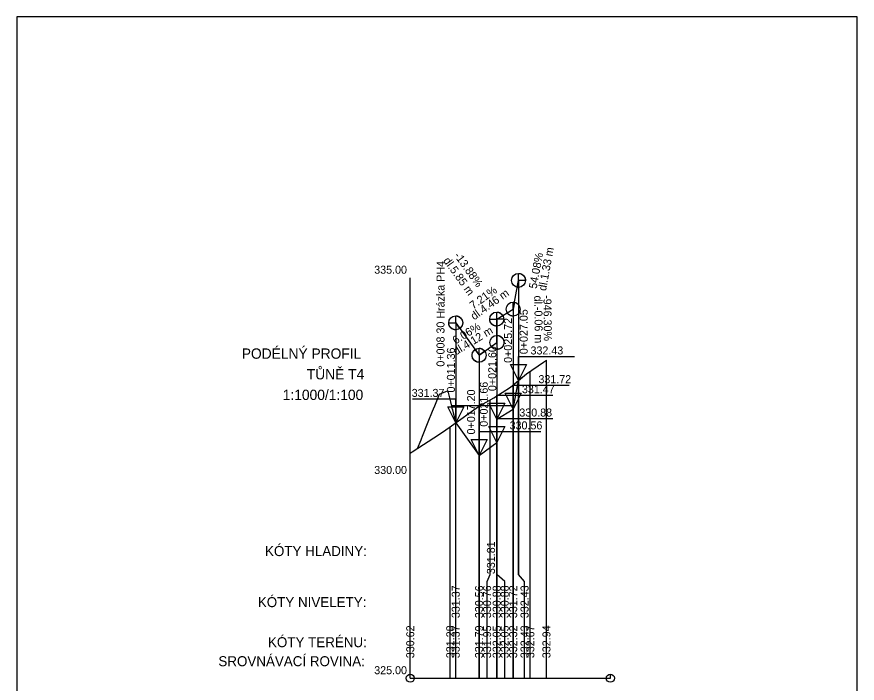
# Model space of a CAD drawing. Extents: x -559294 to -559084, y -1163838 to -1163541.
# Drawn here: x -559293.9 to -559083.9, y -1163707.7 to -1163541.3 of the extents above; entities that cross this region are included whole.
import ezdxf

# ---------------------------------------------------------------- set-up
doc = ezdxf.new("R2010")
doc.units = 0
for name, color, linetype in [('13', 7, 'Continuous'), ('14', 7, 'Continuous'), ('16', 7, 'Continuous'), ('4', 7, 'Continuous'), ('46', 7, 'Continuous'), ('56', 7, 'Continuous'), ('8', 7, 'Continuous'), ('_PP', 7, 'Continuous')]:
    doc.layers.add(name, color=color, linetype=linetype)

msp = doc.modelspace()

# ---------------------------------------------------------------- linework, layer by layer
for p, q in [((-559083.87, -1163541.29), (-559293.87, -1163541.29)), ((-559293.87, -1163541.29), (-559293.87, -1163838.29)), ((-559083.87, -1163838.29), (-559083.87, -1163541.29)), ((-559184.19, -1163617.69), (-559184.19, -1163642.69)), ((-559161.52, -1163706.43), (-559161.52, -1163627.03)), ((-559165.55, -1163706.43), (-559165.55, -1163629.73)), ((-559169.83, -1163639.26), (-559168.5, -1163632.09)), ((-559169.83, -1163706.43), (-559169.83, -1163633.23)), ((-559173.95, -1163706.43), (-559173.95, -1163635.93)), ((-559178.35, -1163706.43), (-559178.35, -1163638.53)), ((-559173.95, -1163641.76), (-559169.83, -1163639.26)), ((-559184.19, -1163642.69), (-559178.35, -1163650.8)), ((-559184.19, -1163706.43), (-559184.19, -1163642.73)), ((-559173.95, -1163641.76), (-559173.89, -1163647.59)), ((-559185.55, -1163706.43), (-559185.55, -1163643.63)), ((-559178.35, -1163650.8), (-559173.89, -1163647.59)), ((-559195.55, -1163706.43), (-559195.55, -1163650.23)), ((-559176.35, -1163706.43), (-559176.35, -1163682.29)), ((-559171.95, -1163706.43), (-559171.95, -1163682.29)), ((-559166.99, -1163706.43), (-559166.99, -1163682.29))]:
    msp.add_line(p, q)
for points in [[(-559195.55, -1163650.25), (-559195.05, -1163649.9), (-559188.27, -1163645.53), (-559187.67, -1163645.07), (-559187.22, -1163644.8), (-559185.26, -1163643.45), (-559178.49, -1163638.58), (-559174.68, -1163636.43), (-559170.51, -1163633.76), (-559166.5, -1163630.43), (-559162.29, -1163627.5), (-559161.52, -1163627.01)], [(-559166.99, -1163682.29), (-559168.5, -1163680.54), (-559168.5, -1163632.13)], [(-559167.71, -1163631.44), (-559167.34, -1163631.13)], [(-559193.72, -1163649.05), (-559192.85, -1163646.89), (-559192.75, -1163646.62), (-559192.48, -1163645.96), (-559191.04, -1163642.38), (-559189.98, -1163639.77), (-559189.73, -1163639.14), (-559189.42, -1163638.39), (-559188.25, -1163635.48), (-559188.05, -1163635.4), (-559187.23, -1163635.08), (-559187.13, -1163635.03), (-559187.04, -1163635), (-559186.81, -1163634.91), (-559186.67, -1163634.85), (-559186.22, -1163634.67), (-559186.12, -1163635.04), (-559186.1, -1163635.13), (-559185.51, -1163637.44), (-559185.23, -1163638.54), (-559185.12, -1163638.97), (-559185.01, -1163639.43), (-559184.81, -1163640.19), (-559184.42, -1163641.72), (-559184.35, -1163641.99), (-559184.18, -1163642.68)], [(-559176.35, -1163682.29), (-559175.55, -1163680.54), (-559175.55, -1163636.93)], [(-559171.95, -1163682.29), (-559173.89, -1163680.54), (-559173.89, -1163635.93)], [(-559185.29, -1163638.32), (-559169.65, -1163638.32)]]:
    msp.add_lwpolyline(points)
for centre in [(-559195.55, -1163706.43), (-559145.55, -1163706.43)]:
    msp.add_circle(centre, 1)
at = {"layer": '14'}
for p, q in [((-559169.83, -1163614.26), (-559168.5, -1163607.09)), ((-559168.5, -1163607.09), (-559168.5, -1163680.54)), ((-559173.95, -1163616.76), (-559169.83, -1163614.26)), ((-559169.83, -1163614.26), (-559169.83, -1163706.43)), ((-559184.19, -1163617.69), (-559184.19, -1163617.69)), ((-559184.19, -1163617.69), (-559178.35, -1163625.8)), ((-559173.89, -1163622.59), (-559173.95, -1163616.76)), ((-559173.95, -1163616.76), (-559173.95, -1163706.43)), ((-559178.35, -1163625.8), (-559173.89, -1163622.59)), ((-559173.89, -1163622.59), (-559173.89, -1163680.54)), ((-559178.35, -1163625.8), (-559178.35, -1163706.43)), ((-559169.83, -1163639.26), (-559168.5, -1163632.09)), ((-559169.83, -1163639.26), (-559168.5, -1163632.09)), ((-559169.83, -1163639.26), (-559168.5, -1163632.09)), ((-559168.5, -1163632.09), (-559168.5, -1163680.54)), ((-559173.95, -1163641.76), (-559169.83, -1163639.26)), ((-559173.95, -1163641.76), (-559169.83, -1163639.26)), ((-559173.95, -1163641.76), (-559169.83, -1163639.26)), ((-559169.83, -1163639.26), (-559169.83, -1163706.43)), ((-559184.19, -1163642.69), (-559178.35, -1163650.8)), ((-559184.19, -1163642.69), (-559178.35, -1163650.8)), ((-559184.19, -1163642.69), (-559184.19, -1163642.69)), ((-559184.19, -1163642.69), (-559178.35, -1163650.8)), ((-559173.95, -1163641.76), (-559173.89, -1163647.59)), ((-559173.95, -1163641.76), (-559173.89, -1163647.59)), ((-559173.89, -1163647.59), (-559173.95, -1163641.76)), ((-559173.95, -1163641.76), (-559173.95, -1163706.43)), ((-559178.35, -1163650.8), (-559173.89, -1163647.59)), ((-559178.35, -1163650.8), (-559173.89, -1163647.59)), ((-559178.35, -1163650.8), (-559173.89, -1163647.59)), ((-559173.89, -1163647.59), (-559173.89, -1163680.54)), ((-559178.35, -1163650.8), (-559178.35, -1163706.43))]:
    msp.add_line(p, q, dxfattribs=at)
at = {"layer": '46'}
for points in [[(-559168.5, -1163607.09), (-559168.5, -1163605.34), (-559168.39, -1163605.35), (-559168.28, -1163605.36), (-559168.17, -1163605.38), (-559168.06, -1163605.4), (-559167.95, -1163605.43), (-559167.84, -1163605.47), (-559167.74, -1163605.52), (-559167.64, -1163605.57), (-559167.55, -1163605.63), (-559167.45, -1163605.69), (-559167.37, -1163605.76), (-559167.28, -1163605.84), (-559167.21, -1163605.92), (-559167.13, -1163606), (-559167.07, -1163606.09), (-559167, -1163606.19), (-559166.95, -1163606.28), (-559166.9, -1163606.39), (-559166.86, -1163606.49), (-559166.82, -1163606.6), (-559166.8, -1163606.7), (-559166.77, -1163606.81), (-559166.76, -1163606.93), (-559166.75, -1163607.04), (-559166.75, -1163607.09), (-559168.5, -1163607.09), (-559168.5, -1163608.84), (-559168.61, -1163608.84), (-559168.73, -1163608.83), (-559168.82, -1163608.81)], [(-559169.83, -1163614.26), (-559169.83, -1163612.51), (-559169.71, -1163612.51), (-559169.6, -1163612.52), (-559169.51, -1163612.54), (-559169.83, -1163614.26), (-559169.83, -1163616.01), (-559169.94, -1163616.01), (-559170.05, -1163616), (-559170.16, -1163615.98), (-559170.27, -1163615.95), (-559170.38, -1163615.92), (-559170.48, -1163615.88), (-559170.59, -1163615.84), (-559170.69, -1163615.78), (-559170.78, -1163615.73), (-559170.87, -1163615.66), (-559170.96, -1163615.59), (-559171.04, -1163615.52), (-559171.12, -1163615.44), (-559171.19, -1163615.35), (-559171.26, -1163615.26), (-559171.32, -1163615.17), (-559171.32, -1163615.17)], [(-559184.19, -1163617.69), (-559184.19, -1163615.94), (-559184.08, -1163615.94), (-559183.97, -1163615.95), (-559183.86, -1163615.97), (-559183.75, -1163615.99), (-559183.64, -1163616.03), (-559183.54, -1163616.06), (-559183.43, -1163616.11), (-559183.34, -1163616.16), (-559183.24, -1163616.22), (-559183.15, -1163616.28), (-559183.06, -1163616.35), (-559182.98, -1163616.43), (-559182.9, -1163616.51), (-559182.83, -1163616.6), (-559182.76, -1163616.68), (-559182.7, -1163616.78), (-559182.64, -1163616.88), (-559182.59, -1163616.98), (-559182.55, -1163617.08), (-559182.52, -1163617.19), (-559182.49, -1163617.3), (-559182.47, -1163617.41), (-559182.45, -1163617.52), (-559182.44, -1163617.63), (-559182.44, -1163617.74), (-559182.45, -1163617.85), (-559182.47, -1163617.97), (-559182.49, -1163618.08), (-559182.52, -1163618.18), (-559182.55, -1163618.29), (-559182.59, -1163618.39), (-559182.64, -1163618.5), (-559182.7, -1163618.59), (-559182.76, -1163618.69), (-559182.83, -1163618.78), (-559182.9, -1163618.86), (-559182.98, -1163618.94), (-559183.06, -1163619.02), (-559183.15, -1163619.09), (-559183.17, -1163619.11), (-559184.19, -1163617.69), (-559184.19, -1163619.44), (-559184.31, -1163619.43), (-559184.42, -1163619.42), (-559184.53, -1163619.4), (-559184.64, -1163619.38), (-559184.75, -1163619.35), (-559184.85, -1163619.31), (-559184.95, -1163619.26), (-559185.05, -1163619.21), (-559185.15, -1163619.15), (-559185.24, -1163619.09), (-559185.33, -1163619.02), (-559185.41, -1163618.94), (-559185.49, -1163618.86), (-559185.56, -1163618.78), (-559185.63, -1163618.69), (-559185.69, -1163618.59), (-559185.75, -1163618.5), (-559185.79, -1163618.39), (-559185.84, -1163618.29), (-559185.87, -1163618.18), (-559185.9, -1163618.08), (-559185.92, -1163617.97), (-559185.94, -1163617.85), (-559185.94, -1163617.74), (-559185.94, -1163617.69)], [(-559173.95, -1163616.76), (-559173.95, -1163615.01), (-559173.84, -1163615.01), (-559173.73, -1163615.02), (-559173.62, -1163615.04), (-559173.51, -1163615.07), (-559173.4, -1163615.1), (-559173.29, -1163615.14), (-559173.19, -1163615.18), (-559173.09, -1163615.23), (-559173, -1163615.29), (-559172.9, -1163615.36), (-559172.82, -1163615.43), (-559172.73, -1163615.5), (-559172.65, -1163615.58), (-559172.58, -1163615.67), (-559172.52, -1163615.76), (-559172.45, -1163615.85), (-559172.4, -1163615.95), (-559172.35, -1163616.05), (-559172.31, -1163616.15), (-559172.27, -1163616.26), (-559172.24, -1163616.37), (-559172.22, -1163616.48), (-559172.21, -1163616.59), (-559172.2, -1163616.7), (-559172.2, -1163616.76), (-559173.95, -1163616.76), (-559173.95, -1163618.51), (-559174.06, -1163618.51), (-559174.17, -1163618.49), (-559174.28, -1163618.48), (-559174.39, -1163618.45), (-559174.5, -1163618.42), (-559174.61, -1163618.38), (-559174.71, -1163618.34), (-559174.81, -1163618.28), (-559174.91, -1163618.23), (-559175, -1163618.16), (-559175.08, -1163618.09), (-559175.17, -1163618.02), (-559175.25, -1163617.94), (-559175.32, -1163617.85), (-559175.39, -1163617.76), (-559175.45, -1163617.67), (-559175.5, -1163617.57), (-559175.55, -1163617.47), (-559175.59, -1163617.36), (-559175.63, -1163617.26), (-559175.66, -1163617.15), (-559175.68, -1163617.04), (-559175.69, -1163616.93), (-559175.7, -1163616.82), (-559175.7, -1163616.76)], [(-559173.89, -1163622.59), (-559173.89, -1163620.84), (-559173.78, -1163620.84), (-559173.67, -1163620.85), (-559173.55, -1163620.87), (-559173.44, -1163620.89), (-559173.34, -1163620.92), (-559173.23, -1163620.96), (-559173.13, -1163621.01), (-559173.03, -1163621.06), (-559172.93, -1163621.12), (-559172.84, -1163621.18), (-559172.75, -1163621.25), (-559172.67, -1163621.33), (-559172.59, -1163621.41), (-559172.52, -1163621.49), (-559172.45, -1163621.58), (-559172.39, -1163621.68), (-559172.34, -1163621.78), (-559172.29, -1163621.88), (-559172.25, -1163621.98), (-559172.21, -1163622.09), (-559172.18, -1163622.2), (-559172.16, -1163622.31), (-559172.15, -1163622.42), (-559172.14, -1163622.53), (-559172.14, -1163622.64), (-559172.15, -1163622.75), (-559172.16, -1163622.86), (-559172.18, -1163622.97), (-559172.21, -1163623.08), (-559172.25, -1163623.19), (-559172.29, -1163623.29), (-559172.34, -1163623.4), (-559172.39, -1163623.49), (-559172.45, -1163623.59), (-559172.52, -1163623.68), (-559172.59, -1163623.76), (-559172.67, -1163623.84), (-559172.75, -1163623.92), (-559172.84, -1163623.99), (-559172.93, -1163624.05), (-559173.03, -1163624.11), (-559173.13, -1163624.16), (-559173.23, -1163624.21), (-559173.34, -1163624.25), (-559173.44, -1163624.28), (-559173.55, -1163624.3), (-559173.67, -1163624.32), (-559173.78, -1163624.33), (-559173.89, -1163622.59), (-559173.89, -1163622.59), (-559173.89, -1163624.34), (-559174, -1163624.33), (-559174.11, -1163624.32), (-559174.22, -1163624.3), (-559174.33, -1163624.28), (-559174.44, -1163624.25), (-559174.55, -1163624.21), (-559174.65, -1163624.16), (-559174.75, -1163624.11), (-559174.84, -1163624.05), (-559174.94, -1163623.99), (-559175.02, -1163623.92), (-559175.11, -1163623.84), (-559175.18, -1163623.76), (-559175.26, -1163623.68), (-559175.31, -1163623.61)], [(-559178.35, -1163625.8), (-559178.35, -1163624.05), (-559178.23, -1163624.05), (-559178.12, -1163624.06), (-559178.01, -1163624.08), (-559177.9, -1163624.11), (-559177.8, -1163624.14), (-559177.69, -1163624.18), (-559177.59, -1163624.22), (-559177.49, -1163624.27), (-559177.39, -1163624.33), (-559177.3, -1163624.4), (-559177.21, -1163624.47), (-559177.13, -1163624.54), (-559177.05, -1163624.62), (-559176.98, -1163624.71), (-559176.93, -1163624.78), (-559178.35, -1163625.8), (-559178.35, -1163627.55), (-559178.46, -1163627.55), (-559178.57, -1163627.53), (-559178.68, -1163627.52), (-559178.79, -1163627.49), (-559178.9, -1163627.46), (-559179, -1163627.42), (-559179.11, -1163627.38), (-559179.21, -1163627.32), (-559179.3, -1163627.27), (-559179.39, -1163627.2), (-559179.48, -1163627.13), (-559179.56, -1163627.06), (-559179.64, -1163626.98), (-559179.72, -1163626.89), (-559179.78, -1163626.8), (-559179.84, -1163626.71), (-559179.9, -1163626.61), (-559179.95, -1163626.51), (-559179.99, -1163626.4), (-559180.02, -1163626.3), (-559180.05, -1163626.19), (-559180.07, -1163626.08), (-559180.09, -1163625.97), (-559180.1, -1163625.85), (-559180.1, -1163625.74), (-559180.09, -1163625.63), (-559180.07, -1163625.52), (-559180.05, -1163625.41), (-559180.02, -1163625.3), (-559179.99, -1163625.19), (-559179.95, -1163625.09), (-559179.9, -1163624.99), (-559179.84, -1163624.89), (-559179.78, -1163624.8), (-559179.72, -1163624.71), (-559179.64, -1163624.62), (-559179.56, -1163624.54), (-559179.48, -1163624.47), (-559179.39, -1163624.4), (-559179.37, -1163624.38)], [(-559168.5, -1163632.09), (-559170.5, -1163628.09), (-559166.5, -1163628.09)], [(-559169.83, -1163639.26), (-559171.83, -1163635.26), (-559167.83, -1163635.26)], [(-559184.19, -1163642.69), (-559186.19, -1163638.69), (-559182.19, -1163638.69)], [(-559173.95, -1163641.76), (-559175.95, -1163637.76), (-559171.95, -1163637.76)], [(-559173.89, -1163647.59), (-559175.89, -1163643.59), (-559171.89, -1163643.59)], [(-559178.35, -1163650.8), (-559180.35, -1163646.8), (-559176.35, -1163646.8)]]:
    msp.add_lwpolyline(points, close=True, dxfattribs=at)
for centre in [(-559168.5, -1163607.09), (-559169.83, -1163614.26), (-559184.19, -1163617.69), (-559173.95, -1163616.76), (-559173.89, -1163622.59), (-559178.35, -1163625.8)]:
    msp.add_circle(centre, 1.75, dxfattribs=at)
at = {"layer": '56'}
for p, q in [((-559195.55, -1163706.43), (-559195.55, -1163606.43)), ((-559195.55, -1163706.43), (-559195.55, -1163705.43)), ((-559195.55, -1163706.43), (-559145.55, -1163706.43)), ((-559145.55, -1163706.43), (-559145.55, -1163705.43))]:
    msp.add_line(p, q, dxfattribs=at)
at = {"layer": '8'}
for p, q in [((-559168.5, -1163632.09), (-559168.5, -1163626.09)), ((-559168.5, -1163626.09), (-559154.5, -1163626.09)), ((-559169.83, -1163639.26), (-559169.83, -1163633.26)), ((-559169.83, -1163633.26), (-559155.83, -1163633.26)), ((-559194.95, -1163636.69), (-559184.19, -1163636.69)), ((-559184.19, -1163642.69), (-559184.19, -1163636.69)), ((-559173.95, -1163641.76), (-559173.95, -1163635.76)), ((-559173.95, -1163635.76), (-559159.95, -1163635.76)), ((-559173.89, -1163647.59), (-559173.89, -1163641.59)), ((-559173.89, -1163641.59), (-559159.89, -1163641.59)), ((-559178.35, -1163650.8), (-559178.35, -1163644.8)), ((-559178.35, -1163644.8), (-559162.88, -1163644.8))]:
    msp.add_line(p, q, dxfattribs=at)

# ---------------------------------------------------------------- texts
for s, p in [('331.81', (-559174.39, -1163680.44)), ('331.37', (-559183.19, -1163691.43)), ('330.56', (-559177.35, -1163691.43)), ('330.76', (-559175.35, -1163691.43)), ('330.88', (-559172.95, -1163691.43)), ('330.88', (-559170.95, -1163691.43)), ('331.72', (-559168.83, -1163691.43)), ('332.43', (-559165.99, -1163691.43)), ('330.62', (-559194.55, -1163701.43)), ('331.28', (-559184.55, -1163701.43)), ('331.37', (-559183.19, -1163701.43)), ('331.79', (-559177.35, -1163701.43)), ('331.95', (-559175.35, -1163701.43)), ('332.05', (-559172.95, -1163701.43)), ('332.05', (-559170.95, -1163701.43)), ('332.32', (-559168.83, -1163701.43)), ('332.43', (-559165.99, -1163701.43)), ('332.67', (-559164.55, -1163701.43)), ('332.94', (-559160.52, -1163701.43))]:
    msp.add_text(s, height=2, rotation=90).set_placement(p)
for s, p in [(' KÓTY NIVELETY:', (-559234.56, -1163688.68)), (' KÓTY TERÉNU:', (-559232.03, -1163698.68))]:
    msp.add_text(s, height=2.5).set_placement(p)
at = {"layer": '13'}
for s, height, p in [('335.00', 2, (-559204.55, -1163605.43)), ('335.00', 2, (-559204.55, -1163605.43)), ('330.00', 2, (-559204.55, -1163655.43)), ('KÓTY HLADINY:', 2.5, (-559231.84, -1163675.93)), ('SROVNÁVACÍ ROVINA:', 2.5, (-559243.49, -1163703.43)), ('325.00', 2, (-559204.55, -1163705.43))]:
    msp.add_text(s, height=height, dxfattribs=at).set_placement(p)
at = {"layer": '16'}
for s, rotation, p in [('dl.1.33 m', 79.5241, (-559161.65, -1163609.83)), ('dl.5.85 m', 305.781, (-559187.42, -1163602.17)), ('-13.88%', 305.781, (-559184.7, -1163600.92)), ('54.08%', 79.5241, (-559163.98, -1163609.31)), ('7.21%', 35.781, (-559179.81, -1163614.41)), ('dl.4.46 m', 35.781, (-559179.57, -1163617.11)), ('dl.-0.06 m', 270.6054, (-559164.55, -1163610.9)), ('-946.30%', 270.6054, (-559162.28, -1163610.79)), ('0+027.05', 90, (-559166.2, -1163625.53)), ('6.06%', 31.2159, (-559184.24, -1163623.12)), ('0+025.72', 90, (-559170.12, -1163627.7)), ('dl.4.12 m', 31.2159, (-559184.08, -1163625.84)), ('0+011.36', 90, (-559184.39, -1163635.09)), ('0+021.60', 90, (-559174.06, -1163634.74)), ('0+021.66', 90, (-559176.18, -1163643.63)), ('0+017.20', 90, (-559179.35, -1163645.56))]:
    msp.add_text(s, height=2, rotation=rotation, dxfattribs=at).set_placement(p)
for s, p in [('332.43', (-559165.5, -1163625.59)), ('331.72', (-559163.52, -1163632.76)), ('331.37', (-559195.19, -1163636.19)), ('331.47', (-559167.64, -1163635.26)), ('330.88', (-559168.29, -1163641.09)), ('330.56', (-559170.72, -1163644.3))]:
    msp.add_text(s, height=2, dxfattribs=at).set_placement(p)
at = {"layer": '4'}
for s, height, p in [('PODÉLNÝ PROFIL ', 2.5762, (-559237.65, -1163626.66)), ('TŮNĚ T4', 2.576, (-559221.4, -1163631.81)), ('1:1000/1:100', 2.5762, (-559227.41, -1163636.96))]:
    msp.add_text(s, height=height, dxfattribs=at).set_placement(p)
at = {"layer": '_PP'}
msp.add_text('0+008 30 Hrázka PH4', height=2, rotation=90, dxfattribs=at).set_placement((-559186.99, -1163628.63))

doc.saveas('drawing.dxf')
